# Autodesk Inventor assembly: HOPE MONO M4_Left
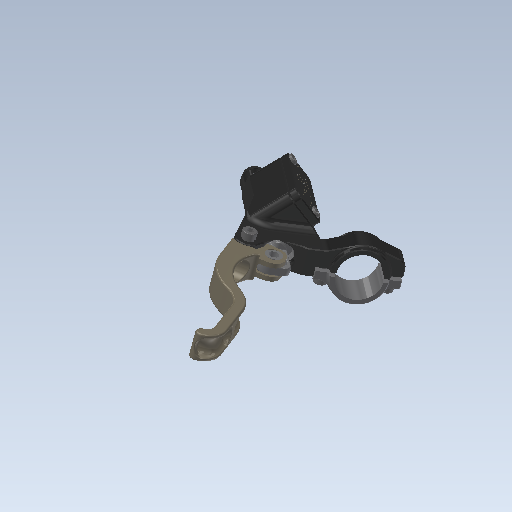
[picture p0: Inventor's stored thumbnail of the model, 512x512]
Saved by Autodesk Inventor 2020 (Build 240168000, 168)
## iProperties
Created: 2017-10
Part Number: HOPE MONO M4_Left
Material: Ogólny
Document SubType Name: Assembly
Designer: Tomasz
Sending System: SolidWorks 2017
Last Author: Tomasz
Last Saved: 2017-10-01
Author: Tomasz
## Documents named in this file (11)
- C:\Users\bruno\Documents\1-Cours-2020-21\1STI2D-2020-21\IT\6. Antivol\Inventor-Antivol\INVENTOR 2018_Steel Hardtail B+\HOPE MONO M4_Left.iam
- C:\Users\bruno\Documents\1-Cours-2020-21\1STI2D-2020-21\IT\6. Antivol\Inventor-Antivol\INVENTOR 2018_Steel Hardtail B+\HOPE MONO M4 klamka_MIR.ipt
- C:\Users\bruno\Documents\1-Cours-2020-21\1STI2D-2020-21\IT\6. Antivol\Inventor-Antivol\INVENTOR 2018_Steel Hardtail B+\HOPE MONO M4 korpus klamki_MIR.ipt
- C:\Users\bruno\Documents\1-Cours-2020-21\1STI2D-2020-21\IT\6. Antivol\Inventor-Antivol\INVENTOR 2018_Steel Hardtail B+\HOPE MONO M4 obejma klamki_MIR.ipt
- C:\Users\bruno\Documents\1-Cours-2020-21\1STI2D-2020-21\IT\6. Antivol\Inventor-Antivol\INVENTOR 2018_Steel Hardtail B+\HOPE MONO M4 pokrywa zbiornika korpusu klamki_MIR.ipt
- C:\Users\bruno\Documents\1-Cours-2020-21\1STI2D-2020-21\IT\6. Antivol\Inventor-Antivol\INVENTOR 2018_Steel Hardtail B+\t_X2_0142_X0_oczek_MIR.ipt
- C:\Users\bruno\Documents\1-Cours-2020-21\1STI2D-2020-21\IT\6. Antivol\Inventor-Antivol\INVENTOR 2018_Steel Hardtail B+\M4 x 6.ipt
- C:\Users\bruno\Documents\1-Cours-2020-21\1STI2D-2020-21\IT\6. Antivol\Inventor-Antivol\INVENTOR 2018_Steel Hardtail B+\ISO 4762 - M4 x 10ISO.ipt
- C:\Users\bruno\Documents\1-Cours-2020-21\1STI2D-2020-21\IT\6. Antivol\Inventor-Antivol\INVENTOR 2018_Steel Hardtail B+\ISO 4762 - M4 x 16ISO.ipt
- C:\Users\bruno\Documents\1-Cours-2020-21\1STI2D-2020-21\IT\6. Antivol\Inventor-Antivol\INVENTOR 2018_Steel Hardtail B+\nakr_X2_0119_X0_tka_MIR.ipt
- C:\Users\bruno\Documents\1-Cours-2020-21\1STI2D-2020-21\IT\6. Antivol\Inventor-Antivol\INVENTOR 2018_Steel Hardtail B+\_X2_01420105_X0_cznik klamki_MIR.ipt
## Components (12 placed, 10 different names)
1. HOPE MONO M4 klamka_MIR:1
2. HOPE MONO M4 korpus klamki_MIR:1
3. HOPE MONO M4 obejma klamki_MIR:1
4. HOPE MONO M4 pokrywa zbiornika korpusu klamki_MIR:1
5. t_X2_0142_X0_oczek_MIR:1
6. M4 x 6:1
7. M4 x 6:2
8. ISO 4762 - M4 x 10ISO:1
9. ISO 4762 - M4 x 10ISO:2
10. ISO 4762 - M4 x 16ISO:1
11. nakr_X2_0119_X0_tka_MIR:1
12. _X2_01420105_X0_cznik klamki_MIR:1
